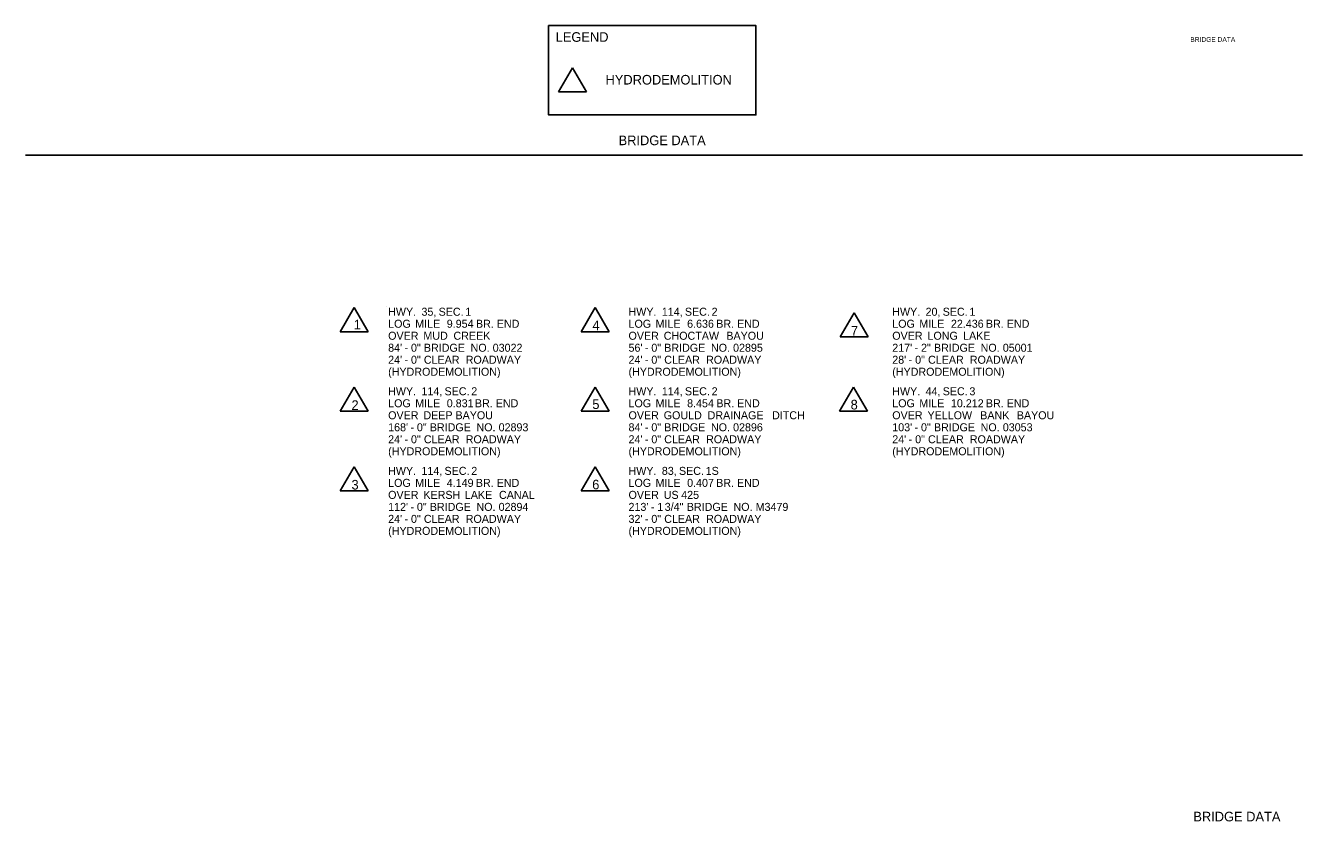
# Model space of a CAD drawing. Extents: x 1930550 to 1932146, y 596452 to 599525.
import ezdxf

# ---------------------------------------------------------------- set-up
doc = ezdxf.new("R2010")
doc.units = 0
for name, color, linetype in [('Default', 7, 'Continuous'), ('R_Border', 7, 'Continuous'), ('R_Border Prem', 7, 'Continuous')]:
    doc.layers.add(name, color=color, linetype=linetype)

msp = doc.modelspace()

# ---------------------------------------------------------------- linework, layer by layer
at = {"layer": 'R_Border'}
for p, q in [((1931233.7, 599472.5), (1931216.3, 599442.4)), ((1931251.1, 599442.4), (1931233.7, 599472.5)), ((1931216.3, 599442.4), (1931251.1, 599442.4)), ((1932145.6, 599363.5), (1930550.2, 599363.5)), ((1930960.9, 599172.9), (1930943.4, 599142.7)), ((1930978.3, 599142.7), (1930960.9, 599172.9)), ((1931001.3, 599174.7), (1931001.3, 599174.7)), ((1931261.9, 599172.9), (1931244.5, 599142.7)), ((1931279.3, 599142.7), (1931261.9, 599172.9)), ((1931585.5, 599166.5), (1931568.1, 599136.4)), ((1931602.9, 599136.4), (1931585.5, 599166.5)), ((1930943.4, 599142.7), (1930978.3, 599142.7)), ((1931244.5, 599142.7), (1931279.3, 599142.7)), ((1931568.1, 599136.4), (1931602.9, 599136.4)), ((1930960.9, 599073.4), (1930943.4, 599043.3)), ((1930978.3, 599043.3), (1930960.9, 599073.4)), ((1931261.9, 599073.4), (1931244.5, 599043.3)), ((1931279.3, 599043.3), (1931261.9, 599073.4)), ((1931584.7, 599073.4), (1931567.3, 599043.3)), ((1931602.1, 599043.3), (1931584.7, 599073.4)), ((1930943.4, 599043.3), (1930978.3, 599043.3)), ((1931244.5, 599043.3), (1931279.3, 599043.3)), ((1931567.3, 599043.3), (1931602.1, 599043.3)), ((1930960.9, 598974), (1930943.4, 598943.8)), ((1930978.3, 598943.8), (1930960.9, 598974)), ((1931261.9, 598974), (1931244.5, 598943.8)), ((1931279.3, 598943.8), (1931261.9, 598974)), ((1930943.4, 598943.8), (1930978.3, 598943.8)), ((1931244.5, 598943.8), (1931279.3, 598943.8))]:
    msp.add_line(p, q, dxfattribs=at)
msp.add_lwpolyline([(1931203.8, 599525.4), (1931462.7, 599525.4), (1931462.7, 599413.8), (1931203.8, 599413.8)], close=True, dxfattribs=at)

# ---------------------------------------------------------------- texts
at = {"layer": 'Default'}
for s, p in [('HWY.', (1931003.3, 599162.7)), (' 35,', (1931041.2, 599162.7)), (' SEC.', (1931062.6, 599162.7)), (' 1', (1931096, 599162.7)), ('HWY.', (1931303.6, 599162.7)), (' 114,', (1931341.5, 599162.7)), (' SEC.', (1931370.3, 599162.7)), (' 2', (1931403.7, 599162.7)), ('HWY.', (1931633.1, 599162.7)), (' 20,', (1931671, 599162.7)), (' SEC.', (1931692.4, 599162.7)), (' 1', (1931725.8, 599162.7)), ('LOG', (1931003.3, 599147.7)), (' MILE', (1931033.4, 599147.7)), (' 9.954', (1931072.8, 599147.7)), (' BR.', (1931109.3, 599147.7)), (' END', (1931135.3, 599147.7)), ('LOG', (1931303.6, 599147.7)), (' MILE', (1931333.7, 599147.7)), (' 6.636', (1931373.1, 599147.7)), (' BR.', (1931409.5, 599147.7)), (' END', (1931435.5, 599147.7)), ('LOG', (1931633.1, 599147.7)), (' MILE', (1931663.2, 599147.7)), (' 22.436', (1931702.7, 599147.7)), (' BR.', (1931746.4, 599147.7)), (' END', (1931772.5, 599147.7)), ('OVER', (1931003.3, 599132.7)), (' MUD', (1931043.6, 599132.7)), (' CREEK', (1931081.2, 599132.7)), ('OVER', (1931303.6, 599132.7)), (' CHOCTAW', (1931343.9, 599132.7)), (' BAYOU', (1931422.1, 599132.7)), ('OVER', (1931633.1, 599132.7)), (' LONG', (1931673.4, 599132.7)), (' LAKE', (1931717.9, 599132.7)), ("84'", (1931003.3, 599117.7)), (' -', (1931020.1, 599117.7)), (' 0"', (1931028.1, 599117.7)), (' BRIDGE', (1931044.2, 599117.7)), (' NO.', (1931102.6, 599117.7)), (' 03022', (1931130.2, 599117.7)), ("56'", (1931303.6, 599117.7)), (' -', (1931320.4, 599117.7)), (' 0"', (1931328.4, 599117.7)), (' BRIDGE', (1931344.5, 599117.7)), (' NO.', (1931402.9, 599117.7)), (' 02895', (1931430.5, 599117.7)), ("217'", (1931633.1, 599117.7)), (' -', (1931657.3, 599117.7)), (' 2"', (1931665.3, 599117.7)), (' BRIDGE', (1931681.5, 599117.7)), (' NO.', (1931739.8, 599117.7)), (' 05001', (1931767.5, 599117.7)), ("24'", (1931003.3, 599102.7)), (' -', (1931020.1, 599102.7)), (' 0"', (1931028.1, 599102.7)), (' CLEAR', (1931044.2, 599102.7)), (' ROADWAY', (1931096.5, 599102.7)), ("24'", (1931303.6, 599102.7)), (' -', (1931320.4, 599102.7)), (' 0"', (1931328.4, 599102.7)), (' CLEAR', (1931344.5, 599102.7)), (' ROADWAY', (1931396.8, 599102.7)), ("28'", (1931633.1, 599102.7)), (' -', (1931649.9, 599102.7)), (' 0"', (1931658, 599102.7)), (' CLEAR', (1931674.1, 599102.7)), (' ROADWAY', (1931726.3, 599102.7)), ('(HYDRODEMOLITION)', (1931003.3, 599087.7)), ('(HYDRODEMOLITION)', (1931303.6, 599087.7)), ('(HYDRODEMOLITION)', (1931633.1, 599087.7)), ('HWY.', (1931003.3, 599063.3)), (' 114,', (1931041.2, 599063.3)), (' SEC.', (1931070, 599063.3)), (' 2', (1931103.4, 599063.3)), ('HWY.', (1931303.6, 599063.3)), (' 114,', (1931341.5, 599063.3)), (' SEC.', (1931370.3, 599063.3)), (' 2', (1931403.7, 599063.3)), ('HWY.', (1931633.1, 599063.3)), (' 44,', (1931671, 599063.3)), (' SEC.', (1931692.4, 599063.3)), (' 3', (1931725.8, 599063.3)), ('LOG', (1931003.3, 599048.3)), (' MILE', (1931033.4, 599048.3)), (' 0.831', (1931072.8, 599048.3)), (' BR.', (1931108, 599048.3)), (' END', (1931134, 599048.3)), ('LOG', (1931303.6, 599048.3)), (' MILE', (1931333.7, 599048.3)), (' 8.454', (1931373.1, 599048.3)), (' BR.', (1931409.6, 599048.3)), (' END', (1931435.6, 599048.3)), ('LOG', (1931633.1, 599048.3)), (' MILE', (1931663.2, 599048.3)), (' 10.212', (1931702.7, 599048.3)), (' BR.', (1931746.4, 599048.3)), (' END', (1931772.4, 599048.3)), ('OVER', (1931003.3, 599033.3)), (' DEEP', (1931043.6, 599033.3)), (' BAYOU', (1931083.7, 599033.3)), ('OVER', (1931303.6, 599033.3)), (' GOULD', (1931343.9, 599033.3)), (' DRAINAGE', (1931398.7, 599033.3)), (' DITCH', (1931479.2, 599033.3)), ('OVER', (1931633.1, 599033.3)), (' YELLOW', (1931673.4, 599033.3)), (' BANK', (1931739.3, 599033.3)), (' BAYOU', (1931785, 599033.3)), ("168'", (1931003.3, 599018.3)), (' 0"', (1931035.5, 599018.3)), (' BRIDGE', (1931051.6, 599018.3)), (' NO.', (1931109.9, 599018.3)), (' 02893', (1931137.6, 599018.3)), ("84'", (1931303.6, 599018.3)), (' 0"', (1931328.4, 599018.3)), (' BRIDGE', (1931344.5, 599018.3)), (' NO.', (1931402.9, 599018.3)), (' 02896', (1931430.5, 599018.3)), ("103'", (1931633.1, 599018.3)), (' 0"', (1931665.3, 599018.3)), (' BRIDGE', (1931681.5, 599018.3)), (' NO.', (1931739.8, 599018.3)), (' 03053', (1931767.5, 599018.3)), ("24'", (1931003.3, 599003.3)), (' -', (1931027.5, 599018.3)), (' 0"', (1931028.1, 599003.3)), (' CLEAR', (1931044.2, 599003.3)), (' ROADWAY', (1931096.5, 599003.3)), ("24'", (1931303.6, 599003.3)), (' -', (1931320.4, 599018.3)), (' 0"', (1931328.4, 599003.3)), (' CLEAR', (1931344.5, 599003.3)), (' ROADWAY', (1931396.8, 599003.3)), ("24'", (1931633.1, 599003.3)), (' -', (1931657.3, 599018.3)), (' 0"', (1931658, 599003.3)), (' CLEAR', (1931674.1, 599003.3)), (' ROADWAY', (1931726.3, 599003.3)), ('(HYDRODEMOLITION)', (1931003.3, 598988.3)), (' -', (1931020.1, 599003.3)), ('(HYDRODEMOLITION)', (1931303.6, 598988.3)), (' -', (1931320.4, 599003.3)), ('(HYDRODEMOLITION)', (1931633.1, 598988.3)), (' -', (1931649.9, 599003.3)), ('HWY.', (1931003.3, 598963.8)), (' 114,', (1931041.2, 598963.8)), (' SEC.', (1931070, 598963.8)), (' 2', (1931103.4, 598963.8)), ('HWY.', (1931303.6, 598963.8)), (' 83,', (1931341.5, 598963.8)), (' SEC.', (1931362.9, 598963.8)), (' 1S', (1931396.3, 598963.8)), ('LOG', (1931003.3, 598948.8)), (' MILE', (1931033.4, 598948.8)), (' 4.149', (1931072.8, 598948.8)), (' BR.', (1931109.1, 598948.8)), (' END', (1931135.2, 598948.8)), ('LOG', (1931303.6, 598948.8)), (' MILE', (1931333.7, 598948.8)), (' 0.407', (1931373.1, 598948.8)), (' BR.', (1931409.4, 598948.8)), (' END', (1931435.4, 598948.8)), ('OVER', (1931003.3, 598933.8)), ("112'", (1931003.3, 598918.8)), (' 0"', (1931035.5, 598918.8)), (' KERSH', (1931043.6, 598933.8)), (' BRIDGE', (1931051.6, 598918.8)), (' LAKE', (1931095.4, 598933.8)), (' NO.', (1931109.9, 598918.8)), (' 02894', (1931137.6, 598918.8)), (' CANAL', (1931138.1, 598933.8)), ('OVER', (1931303.6, 598933.8)), ("213'", (1931303.6, 598918.8)), (' US', (1931343.9, 598933.8)), (' 3/4"', (1931345.1, 598918.8)), (' 425', (1931365.7, 598933.8)), (' BRIDGE', (1931372.7, 598918.8)), (' NO.', (1931431, 598918.8)), (' M3479', (1931458.7, 598918.8)), ("24'", (1931003.3, 598903.8)), (' -', (1931027.5, 598918.8)), (' 0"', (1931028.1, 598903.8)), (' CLEAR', (1931044.2, 598903.8)), (' ROADWAY', (1931096.5, 598903.8)), ("32'", (1931303.6, 598903.8)), (' -', (1931327.8, 598918.8)), (' 0"', (1931328.4, 598903.8)), (' 1', (1931335.8, 598918.8)), (' CLEAR', (1931344.5, 598903.8)), (' ROADWAY', (1931396.8, 598903.8)), ('(HYDRODEMOLITION)', (1931003.3, 598888.8)), (' -', (1931020.1, 598903.8)), ('(HYDRODEMOLITION)', (1931303.6, 598888.8)), (' -', (1931320.4, 598903.8))]:
    msp.add_text(s, height=10, rotation=360, dxfattribs=at).set_placement(p)
at = {"layer": 'R_Border'}
for s, p in [('LEGEND', (1931212.6, 599505.1)), ('HYDRODEMOLITION', (1931274.9, 599451.7)), ('BRIDGE DATA', (1931291.2, 599375.9)), ('1', (1930960.2, 599145.6)), ('4', (1931258.5, 599144.6)), ('7', (1931581.4, 599137.8)), ('2', (1930957.5, 599045)), ('5', (1931258.4, 599046.1)), ('8', (1931581.1, 599045.6)), ('3', (1930957.5, 598945.5)), ('6', (1931258.2, 598945.7)), ('BRIDGE DATA', (1932009.3, 598530.7))]:
    msp.add_text(s, height=12, rotation=360, dxfattribs=at).set_placement(p)
at = {"layer": 'R_Border Prem'}
msp.add_text('BRIDGE DATA', height=6, rotation=360, dxfattribs=at).set_placement((1932005.5, 599505))

doc.saveas('drawing.dxf')
